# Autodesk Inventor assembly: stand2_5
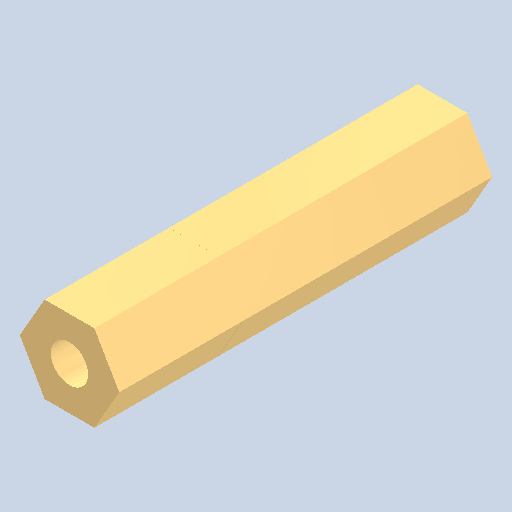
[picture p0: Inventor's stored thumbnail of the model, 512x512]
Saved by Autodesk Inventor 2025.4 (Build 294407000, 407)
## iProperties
Created: 2026-09
Part Number: stand2_5
Document SubType Name: Assembly
Designer: AdminForWorker
Title: stanofff v1
Author: AdminForWorker
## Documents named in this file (3)
- c:\worker\convert-fusion-r05-cosv3\tmp\job-1\19\temp\files\ca3d996b-dda0-445d-8bee-12a194174ca8\stanofff v1_3.iam
- c:\worker\convert-fusion-r05-cosv3\tmp\job-1\19\temp\files\ca3d996b-dda0-445d-8bee-12a194174ca8\M3-10 v1 (2).ipt
- c:\worker\convert-fusion-r05-cosv3\tmp\job-1\19\temp\files\ca3d996b-dda0-445d-8bee-12a194174ca8\M3-20 v1.ipt
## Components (2 placed, 2 different names)
1. M3-10 v1 (2):1
2. M3-20 v1:1
